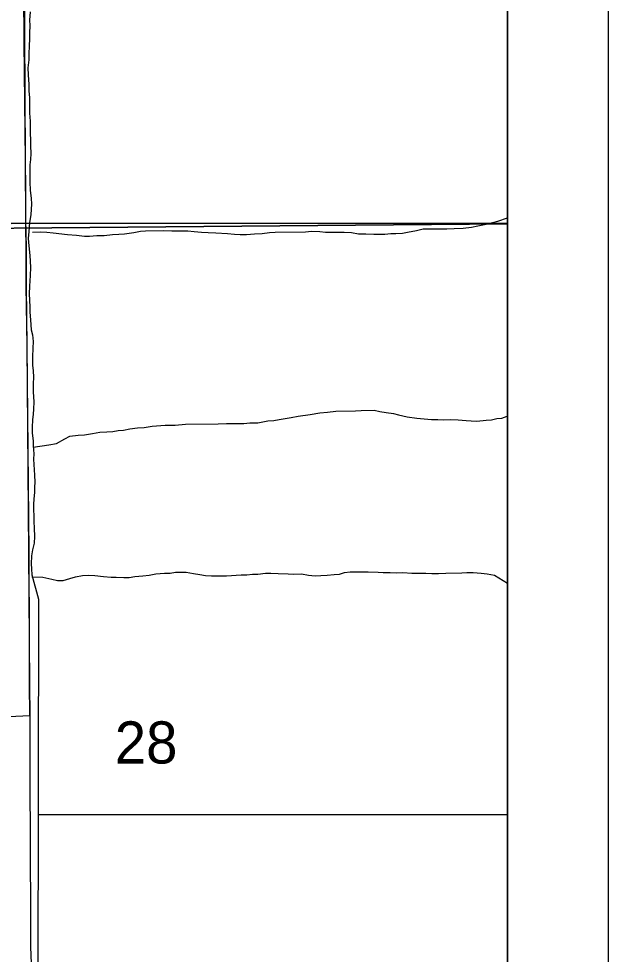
# Model space of a CAD drawing. Extents: x 0 to 34, y 0 to 22.
# Drawn here: x 8.415 to 9, y 16.538 to 17.466 of the extents above; entities that cross this region are included whole.
import ezdxf

# ---------------------------------------------------------------- set-up
doc = ezdxf.new("R2010")
doc.units = 0
for name, color, linetype in [('GM_X_County_Road', 7, 'Continuous'), ('GM_X_Minor_River', 7, 'Continuous'), ('GM_X_Section_Text', 7, 'Continuous'), ('GM_X_State_Route', 7, 'Continuous'), ('GM_X_Township_Road', 7, 'Continuous'), ('GM_X_Unincorporated', 7, 'Continuous'), ('SH_Data', 7, 'Continuous')]:
    doc.layers.add(name, color=color, linetype=linetype)

msp = doc.modelspace()

# ---------------------------------------------------------------- linework, layer by layer
at = {"layer": 'GM_X_County_Road'}
for points in [[(8.42205, 17.26311), (8.42192, 17.29699), (8.42101, 17.38406), (8.42042, 17.44313), (8.4199, 17.49287), (8.41949, 17.52709), (8.41889, 17.5986), (8.41879, 17.6483), (8.41864, 17.69182), (8.41862, 17.77577), (8.41828, 17.88149), (8.41806, 17.92809), (8.41825, 17.97465), (8.41812, 17.99316), (8.41825, 18.02243)], [(8.42609, 16.77439), (8.42578, 16.80573), (8.4257, 16.84926), (8.42525, 16.93632), (8.42337, 17.14154), (8.42263, 17.20062), (8.42245, 17.23482), (8.42212, 17.25769), (8.42205, 17.26311)], [(8.42823, 16.52226), (8.42757, 16.52966), (8.42729, 16.5364), (8.42688, 16.54599), (8.42674, 16.57375), (8.42663, 16.64554), (8.42627, 16.71421), (8.42609, 16.77439)]]:
    msp.add_lwpolyline(points, dxfattribs=at)
at = {"layer": 'GM_X_Minor_River'}
msp.add_line((8.43411, 16.6769), (8.9, 16.67681), dxfattribs=at)
for points in [[(8.42632, 17.47334), (8.42567, 17.46498), (8.42574, 17.45966), (8.42546, 17.45206), (8.42553, 17.44636), (8.42524, 17.4399), (8.42497, 17.43116), (8.42504, 17.42585), (8.424, 17.41786), (8.4241, 17.41064), (8.42498, 17.40115), (8.42506, 17.3947), (8.42553, 17.38825), (8.42573, 17.37268), (8.42621, 17.3647), (8.42629, 17.35863), (8.42653, 17.3404), (8.42701, 17.33281), (8.42671, 17.32672), (8.42602, 17.3214), (8.42574, 17.31304), (8.42586, 17.3043), (8.42634, 17.29633), (8.42721, 17.28799), (8.42766, 17.28267), (8.42704, 17.27203), (8.42561, 17.26441), (8.42497, 17.25529), (8.4243, 17.24844), (8.42477, 17.24123), (8.42604, 17.23137), (8.42611, 17.22605), (8.42658, 17.2196), (8.4263, 17.21162), (8.42568, 17.20098), (8.42539, 17.19338), (8.42547, 17.1873), (8.42595, 17.18009), (8.42601, 17.17515), (8.42649, 17.16756), (8.42738, 17.1577)], [(8.4284, 17.25457), (8.43676, 17.25507), (8.44285, 17.25477), (8.44895, 17.25409), (8.46342, 17.25238), (8.47218, 17.25174), (8.48018, 17.25071), (8.48512, 17.25077), (8.49234, 17.25125), (8.49957, 17.25134), (8.50793, 17.25221), (8.51439, 17.25268), (8.51971, 17.25313), (8.5292, 17.25439), (8.53565, 17.25562), (8.54058, 17.25607), (8.55808, 17.2563), (8.56683, 17.25604), (8.5752, 17.25615), (8.58281, 17.25587), (8.5889, 17.25519), (8.59614, 17.25453), (8.60299, 17.25424), (8.6106, 17.25396), (8.62201, 17.25335), (8.62887, 17.25268), (8.63458, 17.25238), (8.64104, 17.25246), (8.64902, 17.25295), (8.65662, 17.25343), (8.66384, 17.25429), (8.66954, 17.25474), (8.69958, 17.25514), (8.70528, 17.2556), (8.71365, 17.25533), (8.71936, 17.25464), (8.73077, 17.25479), (8.738, 17.25451), (8.74523, 17.25423), (8.75209, 17.25318), (8.75932, 17.25289), (8.76732, 17.25262), (8.77834, 17.25277), (8.78404, 17.25322), (8.78899, 17.25329), (8.79583, 17.25376), (8.80076, 17.25459), (8.80949, 17.25622), (8.81631, 17.25783), (8.8319, 17.25804), (8.83989, 17.25814), (8.84711, 17.25824), (8.85585, 17.25874), (8.86421, 17.25961), (8.87066, 17.26083), (8.88053, 17.26286), (8.89038, 17.26565), (8.89985, 17.26882), (8.9, 17.26885)], [(8.42738, 17.1577), (8.42859, 17.15278), (8.42905, 17.14632), (8.42876, 17.13948), (8.42849, 17.13112), (8.4286, 17.12277), (8.42905, 17.11707), (8.42951, 17.11062), (8.42922, 17.10416), (8.42932, 17.09618), (8.42983, 17.08632), (8.42954, 17.0791), (8.42923, 17.07415), (8.42854, 17.06845), (8.42825, 17.06122), (8.42833, 17.05515), (8.42919, 17.04756), (8.42926, 17.04263), (8.42974, 17.03466), (8.42943, 17.02933), (8.43033, 17.01871), (8.4304, 17.01339), (8.43086, 17.00656), (8.43055, 17.00162), (8.43061, 16.99668), (8.42994, 16.98983), (8.42963, 16.98489), (8.42985, 16.96742), (8.43032, 16.96097), (8.43042, 16.95261), (8.43013, 16.94615), (8.4287, 16.9393), (8.42763, 16.93358), (8.42735, 16.9256), (8.42742, 16.92067), (8.42788, 16.9146), (8.43435, 16.89059)], [(8.42935, 17.04115), (8.44484, 17.04359), (8.45243, 17.04483), (8.46073, 17.0495), (8.46564, 17.05223), (8.474, 17.0531), (8.48008, 17.05356), (8.48805, 17.0548), (8.49526, 17.05604), (8.50248, 17.05651), (8.50818, 17.05697), (8.51349, 17.0578), (8.51881, 17.05825), (8.52526, 17.05948), (8.53286, 17.06034), (8.53932, 17.0608), (8.54729, 17.06205), (8.56021, 17.06298), (8.5701, 17.06311), (8.58035, 17.06401), (8.61268, 17.06444), (8.62104, 17.06493), (8.63283, 17.06471), (8.63816, 17.06478), (8.64423, 17.06561), (8.65222, 17.06534), (8.66208, 17.06737), (8.66816, 17.06783), (8.67348, 17.06866), (8.67917, 17.06988), (8.68524, 17.07072), (8.69207, 17.07195), (8.70422, 17.07363), (8.71371, 17.07528), (8.7213, 17.07614), (8.72966, 17.07701), (8.74905, 17.07726), (8.75475, 17.07772), (8.76768, 17.07789), (8.7734, 17.07683), (8.7795, 17.07577), (8.78674, 17.07473), (8.7917, 17.07327), (8.80047, 17.07149), (8.81, 17.0701), (8.82447, 17.06877), (8.83094, 17.06886), (8.83665, 17.06855), (8.84387, 17.06865), (8.8511, 17.06836), (8.8591, 17.06771), (8.86405, 17.0674), (8.86938, 17.06709), (8.87887, 17.06798), (8.88419, 17.06843), (8.8895, 17.06964), (8.89444, 17.07008), (8.89974, 17.07205), (8.9, 17.07212)], [(8.4279, 16.91259), (8.43893, 16.91246), (8.44771, 16.9103), (8.45343, 16.90886), (8.45914, 16.90893), (8.46558, 16.91092), (8.47126, 16.91251), (8.47809, 16.91412), (8.48455, 16.91421), (8.49026, 16.9139), (8.49902, 16.91288), (8.50664, 16.91222), (8.51158, 16.91229), (8.51919, 16.91201), (8.52451, 16.91208), (8.53021, 16.91292), (8.53818, 16.91378), (8.54426, 16.91424), (8.5511, 16.91547), (8.55945, 16.91634), (8.56516, 16.91642), (8.57047, 16.91725), (8.58112, 16.91739), (8.58836, 16.91597), (8.59446, 16.91491), (8.60018, 16.91385), (8.60627, 16.91355), (8.6211, 16.91375), (8.63554, 16.9147), (8.64124, 16.91477), (8.64694, 16.91523), (8.65227, 16.9153), (8.65986, 16.91616), (8.66519, 16.91623), (8.67242, 16.91595), (8.68231, 16.9157), (8.68764, 16.91539), (8.69562, 16.9155), (8.70248, 16.91445), (8.70896, 16.91377), (8.71466, 16.91385), (8.72112, 16.91432), (8.72796, 16.91479), (8.73328, 16.91524), (8.73821, 16.91682), (8.7439, 16.91766), (8.75036, 16.91774), (8.75607, 16.91744), (8.76178, 16.91751), (8.77167, 16.91727), (8.77662, 16.91695), (8.78346, 16.91704), (8.78955, 16.91674), (8.79602, 16.91683), (8.80515, 16.91619), (8.81885, 16.91637), (8.82493, 16.91607), (8.8314, 16.91578), (8.83863, 16.91626), (8.8546, 16.91647), (8.85953, 16.91692), (8.866, 16.917), (8.87399, 16.91635), (8.87971, 16.91566), (8.88695, 16.91424), (8.9, 16.90646)], [(8.43435, 16.89059), (8.43392, 16.50497), (8.1234, 16.25264), (7.79723, 15.87155), (7.31143, 15.33144), (7.166, 15.28711), (6.9088, 15.11889), (6.39824, 15.00729)]]:
    msp.add_lwpolyline(points, dxfattribs=at)
at = {"layer": 'GM_X_State_Route'}
msp.add_lwpolyline([(7.84206, 17.49846), (7.76632, 17.30128), (7.76351, 17.30242), (7.74392, 17.25141), (7.74731, 17.2514), (7.58333, 16.82444), (7.53463, 16.72006), (7.52459, 16.70266), (7.91569, 16.75061), (8.42588, 16.77494), (8.42557, 16.80628), (8.42549, 16.8498), (8.42504, 16.93686), (8.42316, 17.14208), (8.42242, 17.20117), (8.42224, 17.23536), (8.42184, 17.26366), (8.41804, 18.02298)], dxfattribs=at)
at = {"layer": 'GM_X_Township_Road'}
msp.add_lwpolyline([(5.76745, 15.2711), (6.92264, 15.26437), (7.92825, 15.25953), (7.93058, 15.76582), (7.9301, 16.11339), (7.92977, 16.23675), (7.92979, 16.26862), (7.92972, 16.3619), (7.91628, 17.25204), (8.42184, 17.26366), (8.9, 17.26338), (8.9, 20.89996)], dxfattribs=at)
msp.add_lwpolyline([(5.77049, 14.09996), (8.9, 14.09996), (8.9, 17.26338), (8.42184, 17.26366), (7.91628, 17.25204), (7.92972, 16.3619), (7.92979, 16.26862), (7.92977, 16.23675), (7.9301, 16.11339), (7.93058, 15.76582), (7.92825, 15.25953), (6.92264, 15.26437), (5.76745, 15.2711), (5.76944, 14.85501)], close=True, dxfattribs=at)
at = {"layer": 'GM_X_Unincorporated'}
for points in [[(8.9, 17.26302), (8.9, 18.27692), (7.92171, 18.27008), (7.92008, 17.25434)], [(8.9, 16.26279), (8.9, 17.26302), (7.92008, 17.25434), (7.92004, 16.95796), (7.93409, 16.26707)]]:
    msp.add_lwpolyline(points, close=True, dxfattribs=at)
at = {"layer": 'SH_Data'}
for p, q in [((9, 20.99996), (9, 13.99996)), ((8.9, 20.89996), (8.9, 14.09996))]:
    msp.add_line(p, q, dxfattribs=at)

# ---------------------------------------------------------------- texts
at = {"layer": 'GM_X_Section_Text'}
msp.add_text('28', height=0.041856, rotation=0.00001, dxfattribs=at).set_placement((8.51015, 16.72735))

doc.saveas('drawing.dxf')
